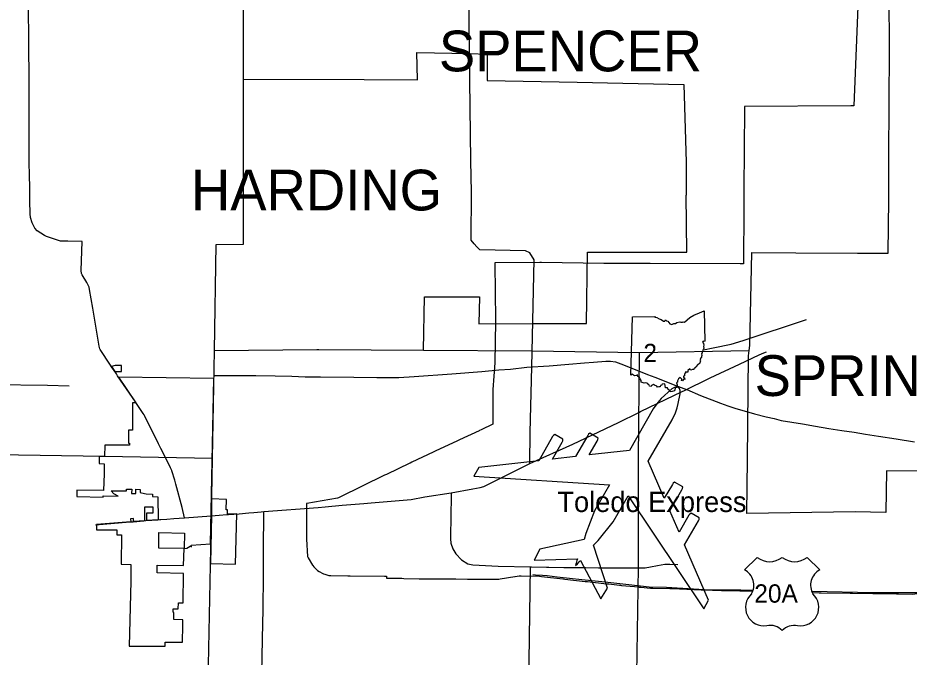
# Model space of a CAD drawing. Extents: x -232 to 448, y 619 to 1059.
# Drawn here: x 68.14 to 113.08, y 897.81 to 930.02 of the extents above; entities that cross this region are included whole.
import ezdxf

# ---------------------------------------------------------------- set-up
doc = ezdxf.new("R2010")
doc.units = 0
doc.layers.add('Default', color=7, linetype='Continuous')

msp = doc.modelspace()

# ---------------------------------------------------------------- linework, layer by layer
at = {"layer": 'Default'}
for p, q in [((99.051, 912.016), (99.133, 914.945)), ((99.051, 912.016), (99.133, 914.945)), ((73.053, 912.501), (72.856, 912.443)), ((72.856, 912.443), (73.028, 912.195)), ((73.372, 912.5), (73.053, 912.501)), ((73.372, 912.194), (73.372, 912.5)), ((73.028, 912.195), (73.372, 912.194)), ((73.725, 909.241), (73.722, 908.593)), ((73.92, 909.24), (73.725, 909.241)), ((73.722, 908.593), (73.773, 908.592)), ((73.773, 908.592), (73.773, 908.479)), ((72.246, 907.915), (72.237, 907.557)), ((72.506, 907.912), (72.246, 907.915)), ((72.237, 907.557), (72.497, 907.552)), ((71.119, 906.224), (71.112, 905.892)), ((72.458, 906.198), (71.119, 906.224)), ((72.447, 905.865), (72.449, 905.927)), ((73.881, 906.267), (73.877, 906.05)), ((74.087, 906.047), (74.09, 906.264)), ((74.923, 906.023), (74.923, 905.893)), ((71.112, 905.892), (72.447, 905.865)), ((74.923, 905.893), (75.198, 905.89)), ((78.663, 905.755), (77.911, 905.777)), ((78.647, 905.236), (78.663, 905.755)), ((78.702, 905.234), (78.647, 905.236)), ((73.967, 904.793), (73.828, 904.78)), ((73.828, 904.78), (73.832, 904.623)), ((73.972, 904.634), (73.967, 904.793)), ((72.105, 904.483), (72.107, 904.216)), ((72.107, 904.216), (73.133, 904.225)), ((73.133, 904.225), (73.135, 903.969)), ((73.135, 903.969), (73.366, 903.971)), ((75.246, 903.303), (75.256, 904.082)), ((76.52, 903.287), (75.246, 903.303)), ((76.494, 902.416), (76.52, 903.287)), ((76.52, 903.287), (76.656, 903.291)), ((76.656, 903.291), (76.821, 903.393)), ((76.821, 903.393), (76.889, 903.357)), ((76.889, 903.357), (76.886, 903.445)), ((105.414, 902.835), (104.78, 902.2)), ((105.414, 902.835), (104.78, 902.2)), ((108.569, 902.2), (107.935, 902.835)), ((108.569, 902.2), (107.935, 902.835)), ((73.842, 902.476), (73.835, 901.633)), ((75.166, 902.051), (75.171, 902.434)), ((75.171, 902.434), (76.494, 902.416)), ((76.487, 902.017), (75.166, 902.051)), ((76.467, 900.54), (76.487, 902.017)), ((73.835, 901.633), (73.752, 898.361)), ((76.224, 900.238), (76.232, 900.546)), ((76.232, 900.546), (76.467, 900.54)), ((75.968, 900.065), (75.973, 900.245)), ((75.973, 900.245), (76.224, 900.238)), ((76.009, 900.064), (75.968, 900.065)), ((76, 899.695), (76.009, 900.064)), ((76.455, 899.683), (76, 899.695))]:
    msp.add_line(p, q, dxfattribs=at)
for points in [[(90.991, 918.82), (91.015, 921.24), (90.986, 922.812), (90.909, 928.215), (90.864, 933.426), (90.807, 938.842), (90.764, 944.289), (90.764, 944.294)], [(110.522, 936.362), (110.545, 933.036), (110.544, 932.963), (110.523, 931.501), (110.519, 931.425), (110.286, 925.582)], [(68.719, 922.826), (68.719, 924.637), (68.714, 927.231), (68.699, 928.352), (68.678, 931.091), (68.668, 933.34)], [(79.52, 926.921), (79.515, 933.612)], [(112.057, 920.929), (112.055, 922.696), (112.064, 926.015), (112.087, 928.105), (112.069, 931.513), (112.553, 931.512), (112.513, 933.427)], [(79.52, 926.921), (85.595, 926.908), (88.284, 926.901), (88.248, 928.271), (90.91, 928.217), (91.798, 928.192), (91.803, 926.861), (96.338, 926.768), (101.715, 926.66), (101.826, 922.737), (101.839, 921.085)], [(78.047, 913.259), (78.144, 918.601), (79.523, 918.607), (79.525, 921.397), (79.52, 926.921)], [(104.774, 925.556), (104.773, 925.504), (104.773, 925.446), (104.742, 921.359)], [(110.286, 925.582), (110.226, 925.584), (110.139, 925.584), (104.774, 925.556)], [(68.752, 920.805), (68.74, 921.564), (68.73, 921.992), (68.719, 922.826)], [(104.742, 921.359), (104.742, 921.322), (104.744, 920.401)], [(70.668, 918.764), (70.292, 918.772), (69.581, 919.003), (69.479, 919.048), (69.108, 919.292), (68.995, 919.417), (68.861, 919.693), (68.785, 919.961), (68.763, 920.139), (68.752, 920.805)], [(88.589, 913.267), (88.634, 915.957), (91.418, 915.964), (91.376, 914.595), (94.076, 914.609), (96.816, 914.622), (96.867, 918.218), (99.542, 918.211), (101.867, 918.212), (101.839, 921.085)], [(105.011, 913.263), (105.047, 913.509), (105.138, 918.189), (107.367, 918.179), (110.478, 918.167), (112.014, 918.162), (112.057, 920.861), (112.057, 920.929)], [(104.744, 920.401), (104.725, 917.676), (104.725, 917.625)], [(72.869, 912.43), (72.811, 912.514), (72.29, 913.299), (72.274, 913.336), (72.233, 913.477), (71.919, 915.387), (71.755, 916.328), (71.732, 916.439), (71.614, 916.683), (71.376, 917.065), (71.348, 917.134), (71.334, 917.28), (71.377, 918.747), (70.668, 918.764)], [(93.951, 907.557), (93.961, 909.127), (94.057, 912.435), (94.167, 917.823), (93.954, 918.183), (93.732, 918.273), (91.426, 918.324), (91.279, 918.472), (91.144, 918.63), (90.991, 918.82)], [(97.792, 917.643), (97.681, 917.645), (94.544, 917.689), (94.455, 917.688), (92.185, 917.679)], [(92.185, 917.679), (92.186, 917.616), (92.228, 914.799), (92.227, 914.74), (92.187, 912.627)], [(104.725, 917.625), (104.563, 917.625), (100.017, 917.633), (99.959, 917.634), (97.792, 917.643)], [(99.133, 914.945), (100.269, 914.964), (100.252, 914.928), (100.359, 914.921), (100.473, 914.858), (100.569, 914.819), (100.687, 914.726), (100.757, 914.727), (100.787, 914.803), (100.841, 914.744), (100.905, 914.734), (101.016, 914.593), (101.107, 914.563), (101.217, 914.611), (101.299, 914.619), (101.359, 914.666), (101.515, 914.707), (101.558, 914.683), (101.641, 914.688), (101.682, 914.706), (101.754, 914.69), (101.881, 914.796), (102.012, 914.922), (102.212, 915.04), (102.512, 915.152), (102.749, 915.253), (102.783, 913.733)], [(99.133, 914.945), (100.269, 914.964), (100.252, 914.928), (100.359, 914.921), (100.473, 914.858), (100.569, 914.819), (100.687, 914.726), (100.757, 914.727), (100.787, 914.803), (100.841, 914.744), (100.905, 914.734), (101.016, 914.593), (101.107, 914.563), (101.217, 914.611), (101.299, 914.619), (101.359, 914.666), (101.515, 914.707), (101.558, 914.683), (101.641, 914.688), (101.682, 914.706), (101.754, 914.69), (101.881, 914.796), (102.012, 914.922), (102.212, 915.04), (102.512, 915.152), (102.749, 915.253), (102.783, 913.733)], [(102.708, 913.298), (103.187, 913.39), (104.098, 913.583), (104.703, 913.754), (107.9, 914.824)], [(102.783, 913.733), (102.748, 913.712), (102.694, 913.722), (102.657, 913.679), (102.703, 913.608), (102.724, 913.533), (102.705, 913.45), (102.724, 913.381), (102.711, 913.324), (102.677, 913.267), (102.665, 913.213), (102.636, 913.156), (102.638, 913.124), (102.61, 913.099), (102.616, 913.004), (102.601, 912.951), (102.606, 912.906), (102.561, 912.894), (102.572, 912.856), (102.543, 912.827), (102.549, 912.777), (102.517, 912.745), (102.548, 912.682), (102.523, 912.661), (102.502, 912.584), (102.444, 912.568), (102.329, 912.426), (102.288, 912.373), (102.242, 912.359), (102.217, 912.304), (102.16, 912.304), (102.075, 912.266), (102.02, 912.331), (101.923, 912.252), (101.912, 912.161), (101.79, 912.164), (101.794, 912.118), (101.767, 912.104), (101.742, 912.058), (101.757, 911.976), (101.7, 911.955), (101.707, 911.907), (101.743, 911.878), (101.759, 911.787), (101.699, 911.805), (101.649, 911.728), (101.598, 911.746), (101.614, 911.812), (101.528, 911.89), (101.446, 911.827), (101.403, 911.727), (101.403, 911.66), (101.342, 911.619), (101.381, 911.524), (101.374, 911.458), (101.375, 911.396), (101.298, 911.398), (101.252, 911.23)], [(102.783, 913.733), (102.748, 913.712), (102.694, 913.722), (102.657, 913.679), (102.703, 913.608), (102.724, 913.533), (102.705, 913.45), (102.724, 913.381), (102.711, 913.324), (102.677, 913.267), (102.665, 913.213), (102.636, 913.156), (102.638, 913.124), (102.61, 913.099), (102.616, 913.004), (102.601, 912.951), (102.606, 912.906), (102.561, 912.894), (102.572, 912.856), (102.543, 912.827), (102.549, 912.777), (102.517, 912.745), (102.548, 912.682), (102.523, 912.661), (102.502, 912.584), (102.444, 912.568), (102.329, 912.426), (102.288, 912.373), (102.242, 912.359), (102.217, 912.304), (102.16, 912.304), (102.075, 912.266), (102.02, 912.331), (101.923, 912.252), (101.912, 912.161), (101.79, 912.164), (101.794, 912.118), (101.767, 912.104), (101.742, 912.058), (101.757, 911.976), (101.7, 911.955), (101.707, 911.907), (101.743, 911.878), (101.759, 911.787), (101.699, 911.805), (101.649, 911.728), (101.598, 911.746), (101.614, 911.812), (101.528, 911.89), (101.446, 911.827), (101.403, 911.727), (101.403, 911.66), (101.342, 911.619), (101.381, 911.524), (101.374, 911.458), (101.375, 911.396), (101.298, 911.398), (101.252, 911.23)], [(77.947, 907.809), (78.047, 913.259)], [(78.047, 913.259), (83.207, 913.314), (83.321, 913.311), (88.589, 913.267)], [(88.589, 913.267), (94.05, 913.245), (99.476, 913.158)], [(99.344, 891.498), (99.352, 896.947), (99.427, 902.322), (99.435, 907.773), (99.476, 913.158)], [(99.476, 913.158), (105.011, 913.263)], [(102.908, 911.807), (103.043, 911.873), (104.517, 912.562), (105.518, 913.043), (105.743, 913.134), (105.879, 913.193)], [(115.144, 907.168), (111.936, 907.2), (111.904, 905.094), (110.356, 905.131), (104.888, 905.043), (104.921, 907.765), (104.984, 912.994), (105.011, 913.263)], [(78.024, 911.989), (80.142, 912.005), (81.115, 911.974), (81.948, 911.957), (82.62, 911.937), (83.393, 911.937), (85.087, 911.917), (86.244, 911.892), (86.811, 911.898), (87.346, 911.9), (88.119, 911.939), (90.022, 912.085), (91.531, 912.204), (92.382, 912.281), (92.977, 912.318), (93.802, 912.412), (94.929, 912.49), (95.926, 912.572), (96.701, 912.639), (97.162, 912.675), (97.788, 912.72), (98.011, 912.711), (98.267, 912.682), (98.548, 912.591), (99.434, 912.236)], [(72.989, 912.254), (72.869, 912.43)], [(73.17, 911.986), (73.109, 912.077), (72.989, 912.254)], [(92.187, 912.627), (92.09, 911.295)], [(99.434, 912.236), (99.887, 912.055)], [(74.067, 910.667), (73.17, 911.986)], [(78.021, 911.848), (73.211, 911.92), (74.096, 910.614), (73.926, 910.627)], [(77.859, 903.518), (78.021, 911.848)], [(101.252, 911.23), (101.12, 911.198), (101.028, 911.178), (100.995, 911.255), (100.929, 911.295), (100.886, 911.372), (100.792, 911.382), (100.77, 911.488), (100.759, 911.574), (100.63, 911.552), (100.594, 911.5), (100.548, 911.486), (100.522, 911.433), (100.459, 911.429), (100.392, 911.404), (100.348, 911.456), (100.239, 911.508), (100.189, 911.535), (100.086, 911.493), (100.064, 911.444), (99.982, 911.465), (99.962, 911.52), (99.913, 911.537), (99.902, 911.595), (99.795, 911.626), (99.714, 911.614), (99.57, 911.661), (99.562, 911.738), (99.513, 911.831), (99.487, 911.896), (99.397, 911.946), (99.378, 912.023), (99.349, 912.02), (99.323, 911.989), (99.222, 911.975), (99.182, 912.006), (99.125, 912.06), (99.051, 912.016)], [(101.252, 911.23), (101.12, 911.198), (101.028, 911.178), (100.995, 911.255), (100.929, 911.295), (100.886, 911.372), (100.792, 911.382), (100.77, 911.488), (100.759, 911.574), (100.63, 911.552), (100.594, 911.5), (100.548, 911.486), (100.522, 911.433), (100.459, 911.429), (100.392, 911.404), (100.348, 911.456), (100.239, 911.508), (100.189, 911.535), (100.086, 911.493), (100.064, 911.444), (99.982, 911.465), (99.962, 911.52), (99.913, 911.537), (99.902, 911.595), (99.795, 911.626), (99.714, 911.614), (99.57, 911.661), (99.562, 911.738), (99.513, 911.831), (99.487, 911.896), (99.397, 911.946), (99.378, 912.023), (99.349, 912.02), (99.323, 911.989), (99.222, 911.975), (99.182, 912.006), (99.125, 912.06), (99.051, 912.016)], [(99.887, 912.055), (100.259, 911.906), (101.31, 911.486), (101.844, 911.289), (101.859, 911.283)], [(101.844, 911.289), (102.908, 911.807)], [(53.508, 911.721), (54.391, 911.705), (56.352, 911.684), (60.081, 911.649), (65.807, 911.561), (66.915, 911.543), (69.643, 911.509), (70.722, 911.472)], [(101.442, 911.41), (101.349, 911.421), (101.3, 911.413), (101.245, 911.396), (101.114, 911.318), (100.739, 910.996), (100.567, 910.832), (100.402, 910.636), (100.178, 910.318), (98.969, 908.223), (96.946, 907.993), (97.351, 908.696), (97.38, 908.766), (97.389, 908.847), (96.979, 909.083), (96.914, 909.035), (96.868, 908.976), (96.255, 907.915), (95.09, 907.783), (95.585, 908.64), (95.614, 908.71), (95.622, 908.791), (95.213, 909.027), (95.147, 908.979), (95.101, 908.92), (94.4, 907.704), (91.382, 907.361), (91.133, 906.929), (97.962, 906.48), (97.209, 905.176), (96.775, 904.043), (96.688, 903.726), (94.456, 903.255), (94.165, 902.699), (96.353, 902.767), (96.315, 902.674), (96.281, 902.549), (96.258, 902.432)], [(96.258, 902.432), (96.349, 902.51), (96.439, 902.602), (96.501, 902.681), (97.536, 900.752), (97.873, 901.282), (97.164, 903.451), (97.395, 903.685), (98.159, 904.627), (98.912, 905.931), (102.716, 900.242), (102.965, 900.674), (101.754, 903.458), (102.455, 904.674), (102.484, 904.743), (102.493, 904.824), (102.083, 905.061), (102.018, 905.012), (101.972, 904.953), (101.476, 904.095), (101.008, 905.171), (101.621, 906.231), (101.649, 906.301), (101.658, 906.382), (101.249, 906.618), (101.183, 906.57), (101.137, 906.511), (100.731, 905.808), (99.919, 907.675), (101.128, 909.77), (101.292, 910.122), (101.379, 910.364), (101.435, 910.594), (101.526, 911.08), (101.528, 911.233), (101.516, 911.288), (101.498, 911.335), (101.442, 911.41)], [(92.09, 911.295), (92.09, 909.541)], [(99.532, 910.175), (101.253, 911.005)], [(101.253, 911.005), (101.844, 911.289)], [(101.859, 911.283), (102.554, 910.986), (103.565, 910.595), (103.928, 910.472), (104.285, 910.345), (105.272, 910.071), (105.874, 909.914), (106.271, 909.822), (106.628, 909.736), (107.702, 909.554), (108.362, 909.444), (109.033, 909.332), (109.677, 909.224), (110.305, 909.135), (110.873, 909.037), (111.522, 908.947), (112.422, 908.8), (113.34, 908.658)], [(73.926, 910.627), (73.92, 909.24)], [(74.465, 910.075), (74.092, 910.631), (74.067, 910.667)], [(75.228, 908.553), (74.537, 909.948), (74.501, 910.02), (74.465, 910.075)], [(89.991, 906.088), (91.071, 906.287), (91.451, 906.358), (91.638, 906.405), (93.951, 907.557), (96.118, 908.543), (98.414, 909.629), (99.443, 910.132), (99.532, 910.175)], [(92.09, 909.541), (91.492, 909.26), (91.418, 909.225), (91.393, 909.214), (90.408, 908.755), (90.341, 908.724), (90.309, 908.709), (89.177, 908.179), (89.105, 908.144), (89.079, 908.132), (87.997, 907.623), (87.913, 907.583), (87.899, 907.577), (86.721, 907.017), (86.673, 906.994)], [(77.947, 907.809), (72.504, 907.924), (67.081, 908.001), (61.61, 908.099), (56.148, 908.205), (50.625, 908.265), (47.884, 908.282), (45.319, 908.301)], [(72.52, 908.487), (72.506, 907.912)], [(73.773, 908.479), (72.52, 908.487)], [(75.352, 908.312), (75.228, 908.553)], [(75.842, 907.344), (75.509, 908.004), (75.352, 908.312)], [(77.412, 880.616), (77.896, 904.964), (77.947, 907.809)], [(72.497, 907.552), (72.485, 907.04), (72.458, 906.198)], [(75.912, 907.197), (75.908, 907.213), (75.842, 907.344)], [(76.111, 906.515), (76.054, 906.725), (75.912, 907.197)], [(86.673, 906.994), (86.623, 906.97), (84.379, 905.86), (84.309, 905.826), (84.264, 905.818), (82.71, 905.546), (82.698, 905.544)], [(76.547, 904.833), (76.423, 905.35), (76.111, 906.515)], [(72.449, 905.927), (73.191, 905.923), (72.981, 906.033), (72.847, 906.188), (73.619, 906.187), (73.621, 906.272), (73.881, 906.267)], [(73.877, 906.05), (74.087, 906.047)], [(74.09, 906.264), (74.302, 906.261)], [(74.302, 906.261), (74.3, 906.096)], [(74.3, 906.096), (74.377, 906.09), (74.607, 906.037), (74.923, 906.023)], [(85.578, 905.549), (85.946, 905.58), (87.971, 905.745), (88.663, 905.876), (89.991, 906.088)], [(89.991, 906.088), (89.968, 904.734), (89.957, 904.034), (89.953, 903.765), (89.973, 903.549), (90.066, 903.268), (90.226, 903.02), (90.509, 902.714), (90.834, 902.515), (91.079, 902.457), (92.361, 902.394), (93.98, 902.356)], [(75.198, 905.89), (75.213, 904.731)], [(77.911, 905.777), (77.896, 904.964)], [(82.698, 905.544), (82.698, 905.533), (82.693, 904.774), (82.693, 904.767), (82.692, 904.666), (82.687, 903.853), (82.686, 903.814), (82.69, 903.748), (82.741, 902.882), (82.741, 902.871), (82.779, 902.81), (83.003, 902.439), (83.013, 902.423), (83.067, 902.364), (83.244, 902.17), (83.331, 902.124), (83.523, 902.023), (83.543, 902.012), (83.616, 901.989), (83.822, 901.921), (83.835, 901.917), (83.914, 901.917), (84.781, 901.909), (84.82, 901.909), (84.89, 901.908), (86.624, 901.891), (86.729, 901.89)], [(84.495, 905.456), (85.144, 905.511)], [(85.144, 905.511), (85.578, 905.549)], [(74.638, 904.686), (74.645, 905.083), (74.961, 905.083), (74.961, 905.367), (74.523, 905.367), (74.523, 904.677)], [(77.847, 902.531), (79.116, 902.499), (79.181, 905.033)], [(78.67, 904.989), (78.754, 904.996), (79.295, 905.033), (79.785, 905.075), (80.037, 905.094), (80.415, 905.127), (80.546, 905.138)], [(78.707, 905.006), (78.702, 905.234)], [(79.181, 905.033), (78.707, 905.006)], [(80.53, 903.138), (80.546, 905.138)], [(80.546, 905.138), (83.282, 905.352), (83.629, 905.381)], [(83.629, 905.381), (84.495, 905.456)], [(72.061, 904.48), (73.791, 904.62)], [(73.832, 904.623), (72.105, 904.483)], [(73.791, 904.62), (73.823, 904.622), (73.953, 904.632)], [(73.953, 904.632), (74.492, 904.674)], [(74.523, 904.677), (73.972, 904.634)], [(74.492, 904.674), (74.6, 904.683)], [(74.6, 904.683), (75.194, 904.729)], [(75.213, 904.731), (74.638, 904.686)], [(75.194, 904.729), (75.302, 904.738)], [(75.302, 904.738), (75.356, 904.742)], [(75.356, 904.742), (75.652, 904.765), (76.005, 904.792)], [(76.005, 904.792), (76.547, 904.833), (77.895, 904.93)], [(77.896, 904.964), (77.847, 902.531)], [(77.895, 904.93), (78.287, 904.957), (78.67, 904.989)], [(73.366, 903.971), (73.357, 902.499), (73.842, 902.476)], [(75.256, 904.082), (76.542, 904.055)], [(76.542, 904.055), (76.52, 903.287)], [(76.886, 903.445), (77.859, 903.518)], [(80.52, 901.949), (80.53, 903.138)], [(93.721, 884.643), (93.821, 888.838), (93.84, 890.285), (93.853, 892.85), (93.98, 902.356)], [(93.98, 902.356), (94.035, 902.355), (94.797, 902.346), (94.81, 902.346), (94.905, 902.344), (95.667, 902.328), (95.686, 902.327), (95.776, 902.326), (96.647, 902.32), (96.661, 902.32), (96.756, 902.319), (97.409, 902.313), (97.429, 902.312), (97.518, 902.312), (98.116, 902.31), (98.136, 902.31), (98.225, 902.31), (98.715, 902.305), (98.77, 902.305), (99.428, 902.311), (99.772, 902.309), (100.041, 902.359), (100.394, 902.429), (100.565, 902.461), (100.756, 902.488), (101.008, 902.497), (101.41, 902.481)], [(80.493, 899.517), (80.506, 900.177), (80.52, 901.949)], [(86.729, 901.89), (86.731, 901.787)], [(91.468, 901.737), (91.523, 901.737), (92.335, 901.738), (92.393, 901.738), (92.451, 901.747), (93.2, 901.863), (93.215, 901.865), (93.308, 901.88), (93.415, 901.898), (93.424, 901.9), (93.514, 901.898), (94.435, 901.883), (94.444, 901.883), (94.538, 901.872), (95.614, 901.751), (95.648, 901.747), (95.722, 901.739), (96.745, 901.625), (96.779, 901.621), (96.853, 901.613), (97.822, 901.505), (97.839, 901.503), (97.93, 901.493), (98.469, 901.434), (98.518, 901.429), (98.577, 901.423), (99.44, 901.341), (99.467, 901.338), (99.548, 901.33), (100.034, 901.285), (100.071, 901.281), (100.146, 901.28), (101.012, 901.261), (101.055, 901.26), (101.12, 901.257), (102.582, 901.202), (102.617, 901.2), (102.69, 901.198), (103.611, 901.171), (103.623, 901.17), (103.72, 901.168), (104.532, 901.146), (104.587, 901.145)], [(94.108, 901.965), (94.239, 901.96), (94.597, 901.937), (94.818, 901.922), (95.323, 901.86), (96.574, 901.713), (97.575, 901.619), (98.945, 901.471), (99.96, 901.352), (100.846, 901.333), (103.033, 901.2), (104.588, 901.196), (105.208, 901.183)], [(86.731, 901.787), (86.733, 901.787), (87.495, 901.778), (87.507, 901.778), (87.603, 901.776), (88.365, 901.759), (88.384, 901.759), (88.474, 901.758), (89.345, 901.752), (89.359, 901.752), (89.454, 901.751), (90.107, 901.744), (90.127, 901.744), (90.216, 901.744), (90.815, 901.742), (90.834, 901.742), (90.923, 901.741), (91.413, 901.737), (91.468, 901.737)], [(104.587, 901.145), (104.641, 901.144), (105.19, 901.132)], [(108.162, 901.123), (111.244, 901.071), (114.058, 901.063), (116.733, 901), (118.426, 900.988)], [(108.187, 901.063), (108.536, 901.055), (108.571, 901.054), (108.645, 901.053), (110.106, 901.035), (110.155, 901.034), (110.214, 901.033), (111.242, 901.012), (111.283, 901.011), (111.351, 901.01), (112.433, 900.995), (112.472, 900.994), (112.541, 900.994), (113.244, 900.986), (113.247, 900.986), (113.355, 900.989), (114.005, 901.01), (114.057, 901.012)], [(76.434, 898.565), (76.451, 899.399), (76.455, 899.683)], [(80.187, 886.165), (80.321, 892.983), (80.445, 897.015), (80.493, 899.517)], [(73.752, 898.361), (75.561, 898.361), (75.561, 898.565), (76.434, 898.565)]]:
    msp.add_lwpolyline(points, dxfattribs=at)
for centre, radius, start, end in [((106.044, 903.636), 1.019, 231.813, 308.187), ((106.044, 903.636), 1.019, 231.813, 308.187), ((107.305, 903.636), 1.019, 231.813, 308.187), ((107.305, 903.636), 1.019, 231.813, 308.187), ((104.383, 901.435), 0.862, 329.1175, 62.6108), ((104.383, 901.435), 0.862, 329.1175, 62.6108), ((108.966, 901.435), 0.862, 117.3892, 210.8825), ((108.966, 901.435), 0.862, 117.3892, 210.8825), ((105.757, 900.312), 0.93, 133.0046, 278.7282), ((105.757, 900.312), 0.93, 133.0046, 278.7282), ((107.591, 900.312), 0.93, 261.2718, 46.9954), ((107.591, 900.312), 0.93, 261.2718, 46.9954), ((106.07, 898.578), 0.832, 43.4177, 101.8742), ((106.07, 898.578), 0.832, 43.4177, 101.8742), ((107.296, 898.523), 0.883, 79.9613, 134.7468), ((107.296, 898.523), 0.883, 79.9613, 134.7468)]:
    msp.add_arc(centre, radius, start, end, dxfattribs=at)

# ---------------------------------------------------------------- texts
for s, height, p in [('SPENCER', 2.052, (89.367, 927.32)), ('HARDING', 2.052, (76.869, 920.313)), (' 2 ', 0.9234, (99.333, 912.669)), ('SPRINGFIELD', 2.052, (105.282, 910.965)), ('Toledo Express             ', 1.026, (95.341, 905.119)), ('20A', 0.9234, (105.268, 900.551))]:
    msp.add_text(s, height=height, dxfattribs=at).set_placement(p)

doc.saveas('drawing.dxf')
